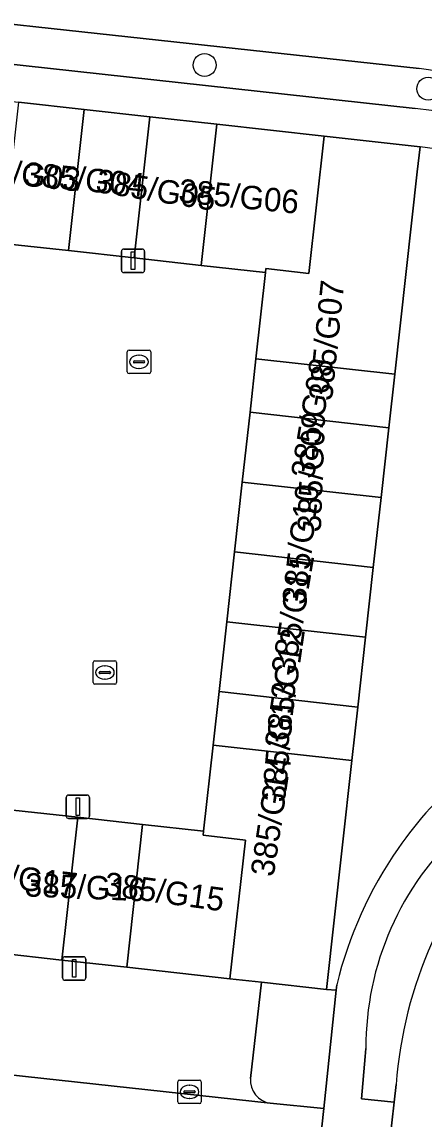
# Model space of a CAD drawing. Extents: x 162026 to 163502, y 387295 to 388169.
# Drawn here: x 162161.01 to 162178.15, y 387792.93 to 387839.64 of the extents above; entities that cross this region are included whole.
import ezdxf

# ---------------------------------------------------------------- set-up
doc = ezdxf.new("R2010")
doc.units = 0
for name, color, linetype in [('IMGEO_Boom', 7, 'Continuous'), ('IMGEO_Fietspad_gesloten', 7, 'Continuous'), ('IMGEO_Groenvoorziening', 7, 'Continuous'), ('IMGEO_Kolk', 7, 'Continuous'), ('IMGEO_Lichtmast', 7, 'Continuous'), ('IMGEO_Pand', 7, 'Continuous'), ('IMGEO_Pand_nummerreeks', 7, 'Continuous'), ('IMGEO_Parkeervlak_open', 7, 'Continuous'), ('IMGEO_Rijbaan_lokaal_open', 7, 'Continuous'), ('IMGEO_Voetpad_open', 7, 'Continuous')]:
    doc.layers.add(name, color=color, linetype=linetype)

msp = doc.modelspace()

# ---------------------------------------------------------------- linework, layer by layer
at = {"layer": 'IMGEO_Boom'}
for centre in [(162168.793, 387837.806), (162178.326, 387836.8)]:
    msp.add_circle(centre, 0.489, dxfattribs=at)
at = {"layer": 'IMGEO_Fietspad_gesloten'}
msp.add_lwpolyline([(162175.011, 387840.691), (162153.864, 387843.037), (162124.015, 387846.348), (162120.863, 387846.697), (162120.645, 387843.913), (162123.707, 387843.579), (162142.441, 387841.533), (162144.47, 387841.312), (162177.938, 387837.659)], dxfattribs=at)
msp.add_arc((162174.885, 387812.883), 24.963, 19.2399, 82.9748, dxfattribs=at)
at = {"layer": 'IMGEO_Groenvoorziening'}
for points in [[(162144.47, 387841.312), (162144.349, 387839.619), (162177.764, 387835.959)], [(162177.938, 387837.659), (162144.47, 387841.312)], [(162177.973, 387834.328), (162177.854, 387833.262), (162176.897, 387824.645), (162176.643, 387822.366), (162176.313, 387819.393), (162175.983, 387816.419), (162175.652, 387813.445), (162175.322, 387810.471), (162175.068, 387808.19), (162174.655, 387804.471), (162173.985, 387798.447), (162174.399, 387798.411), (162174.423, 387798.647)], [(162174.399, 387798.411), (162173.985, 387798.447), (162171.221, 387798.754), (162170.746, 387794.657)], [(162171.589, 387793.598), (162173.877, 387793.382), (162174.399, 387798.411)], [(162175.666, 387795.93), (162175.642, 387795.586), (162175.477, 387793.792), (162176.873, 387793.647), (162176.954, 387794.397)]]:
    msp.add_lwpolyline(points, dxfattribs=at)
for centre, radius, start, end in [((162174.885, 387812.883), 24.963, 19.2399, 82.9748), ((162175.651, 387814.372), 21.69, 25.9544, 84.4086), ((162175.575, 387814.095), 20.374, 26.678, 83.2402), ((162191.407, 387794.495), 17.477, 130.9104, 145.2692), ((162195.063, 387793.031), 18.161, 136.1983, 175.6852), ((162188.185, 387795.99), 12.519, 132.1359, 180.2763), ((162191.436, 387794.462), 17.52, 145.2363, 166.181), ((162171.751, 387794.592), 1.007, 176.3125, 260.7294)]:
    msp.add_arc(centre, radius, start, end, dxfattribs=at)
at = {"layer": 'IMGEO_Kolk'}
for p, q in [((162165.574, 387825.67), (162166.426, 387825.67)), ((162165.499, 387824.744), (162165.499, 387825.596)), ((162165.801, 387825.213), (162166.199, 387825.213)), ((162165.987, 387825.45), (162166.012, 387825.45)), ((162166.5, 387825.596), (162166.5, 387824.744)), ((162165.758, 387825.164), (162165.758, 387825.176)), ((162166.196, 387825.127), (162165.798, 387825.127)), ((162166.01, 387824.89), (162165.985, 387824.89)), ((162166.242, 387825.176), (162166.242, 387825.164)), ((162166.426, 387824.67), (162165.574, 387824.67)), ((162164.045, 387811.514), (162164.045, 387812.366)), ((162164.12, 387812.44), (162164.972, 387812.44)), ((162164.533, 387812.22), (162164.558, 387812.22)), ((162165.046, 387812.366), (162165.046, 387811.514)), ((162164.304, 387811.934), (162164.304, 387811.946)), ((162164.742, 387811.897), (162164.344, 387811.897)), ((162164.347, 387811.983), (162164.745, 387811.983)), ((162164.556, 387811.66), (162164.531, 387811.66)), ((162164.788, 387811.946), (162164.788, 387811.934)), ((162164.972, 387811.44), (162164.12, 387811.44)), ((162167.651, 387793.66), (162167.651, 387794.512)), ((162167.726, 387794.586), (162168.578, 387794.586)), ((162168.139, 387794.366), (162168.164, 387794.366)), ((162168.652, 387794.512), (162168.652, 387793.66)), ((162167.91, 387794.08), (162167.91, 387794.092)), ((162168.348, 387794.043), (162167.95, 387794.043)), ((162167.953, 387794.129), (162168.351, 387794.129)), ((162168.394, 387794.092), (162168.394, 387794.08)), ((162168.578, 387793.586), (162167.726, 387793.586)), ((162168.162, 387793.806), (162168.137, 387793.806))]:
    msp.add_line(p, q, dxfattribs=at)
for points in [[(162165.574, 387825.67), (162166.426, 387825.67)], [(162165.499, 387824.744), (162165.499, 387825.596)], [(162166.5, 387825.596), (162166.5, 387824.744)], [(162166.426, 387824.67), (162165.574, 387824.67)], [(162164.045, 387811.514), (162164.045, 387812.366)], [(162164.12, 387812.44), (162164.972, 387812.44)], [(162165.046, 387812.366), (162165.046, 387811.514)], [(162164.972, 387811.44), (162164.12, 387811.44)], [(162167.651, 387793.66), (162167.651, 387794.512)], [(162167.726, 387794.586), (162168.578, 387794.586)], [(162168.652, 387794.512), (162168.652, 387793.66)], [(162168.578, 387793.586), (162167.726, 387793.586)]]:
    msp.add_lwpolyline(points, dxfattribs=at)
for centre, radius, start, end in [((162165.576, 387825.594), 0.0765, 91.552, 178.448), ((162165.576, 387825.594), 0.0765, 91.552, 178.448), ((162166.424, 387825.594), 0.0765, 1.552, 88.448), ((162166.424, 387825.594), 0.0765, 1.552, 88.448), ((162165.798, 387825.173), 0.0403, 85.8775, 175.7526), ((162166.203, 387825.175), 0.0386, 1.7309, 96.639), ((162165.576, 387824.746), 0.0765, 181.552, 268.448), ((162165.576, 387824.746), 0.0765, 181.552, 268.448), ((162165.795, 387825.163), 0.0366, 178.938, 274.7102), ((162166.199, 387825.17), 0.043, 264.8664, 352.4533), ((162166.424, 387824.746), 0.0765, 271.552, 358.448), ((162166.424, 387824.746), 0.0765, 271.552, 358.448), ((162164.122, 387812.364), 0.0765, 91.552, 178.448), ((162164.122, 387812.364), 0.0765, 91.552, 178.448), ((162164.97, 387812.364), 0.0765, 1.552, 88.448), ((162164.97, 387812.364), 0.0765, 1.552, 88.448), ((162164.344, 387811.943), 0.0403, 85.8775, 175.7526), ((162164.341, 387811.933), 0.0366, 178.938, 274.7102), ((162164.745, 387811.94), 0.043, 264.8664, 352.4533), ((162164.749, 387811.945), 0.0386, 1.7309, 96.639), ((162164.122, 387811.516), 0.0765, 181.552, 268.448), ((162164.122, 387811.516), 0.0765, 181.552, 268.448), ((162164.97, 387811.516), 0.0765, 271.552, 358.448), ((162164.97, 387811.516), 0.0765, 271.552, 358.448), ((162167.728, 387794.51), 0.0765, 91.552, 178.448), ((162167.728, 387794.51), 0.0765, 91.552, 178.448), ((162168.576, 387794.51), 0.0765, 1.552, 88.448), ((162168.576, 387794.51), 0.0765, 1.552, 88.448), ((162167.95, 387794.089), 0.0403, 85.8775, 175.7526), ((162167.947, 387794.079), 0.0366, 178.938, 274.7102), ((162168.351, 387794.086), 0.043, 264.8664, 352.4533), ((162168.355, 387794.091), 0.0386, 1.7309, 96.639), ((162167.728, 387793.662), 0.0765, 181.552, 268.448), ((162167.728, 387793.662), 0.0765, 181.552, 268.448), ((162168.576, 387793.662), 0.0765, 271.552, 358.448), ((162168.576, 387793.662), 0.0765, 271.552, 358.448)]:
    msp.add_arc(centre, radius, start, end, dxfattribs=at)
for centre, major_axis, ratio, start_param, end_param in [((162165.986, 387825.17), (-0.387, 0.002), 0.722429, 4.712389, 7.853982), ((162166.011, 387825.17), (-0.39, 0.002), 0.717154, 1.570796, 4.712389), ((162164.532, 387811.94), (-0.387, 0.002), 0.722429, 4.712389, 7.853982), ((162164.557, 387811.94), (-0.39, 0.002), 0.717154, 1.570796, 4.712389), ((162168.138, 387794.086), (-0.387, 0.002), 0.722429, 4.712389, 7.853982), ((162168.163, 387794.086), (-0.39, 0.002), 0.717154, 1.570796, 4.712389)]:
    msp.add_ellipse(centre, major_axis=major_axis, ratio=ratio, start_param=start_param, end_param=end_param, dxfattribs=at)
at = {"layer": 'IMGEO_Lichtmast'}
for p, q in [((162165.248, 387829.073), (162165.248, 387829.873)), ((162165.248, 387829.873), (162165.248, 387829.073)), ((162165.348, 387829.973), (162166.138, 387829.973)), ((162166.138, 387829.973), (162165.348, 387829.973)), ((162166.238, 387829.873), (162166.238, 387829.073)), ((162166.238, 387829.073), (162166.238, 387829.873)), ((162166.138, 387828.973), (162165.348, 387828.973)), ((162165.348, 387828.973), (162166.138, 387828.973)), ((162162.9, 387805.825), (162162.9, 387806.625)), ((162162.9, 387806.625), (162162.9, 387805.825)), ((162163, 387806.725), (162163.79, 387806.725)), ((162163.79, 387806.725), (162163, 387806.725)), ((162163.89, 387806.625), (162163.89, 387805.825)), ((162163.89, 387805.825), (162163.89, 387806.625)), ((162163.79, 387805.725), (162163, 387805.725)), ((162163, 387805.725), (162163.79, 387805.725)), ((162162.743, 387798.94), (162162.743, 387799.74)), ((162162.743, 387799.74), (162162.743, 387798.94)), ((162162.843, 387799.84), (162163.633, 387799.84)), ((162163.633, 387799.84), (162162.843, 387799.84)), ((162163.733, 387799.74), (162163.733, 387798.94)), ((162163.733, 387798.94), (162163.733, 387799.74)), ((162163.633, 387798.84), (162162.843, 387798.84)), ((162162.843, 387798.84), (162163.633, 387798.84))]:
    msp.add_line(p, q, dxfattribs=at)
for points in [[(162165.668, 387829.848), (162165.818, 387829.848), (162165.818, 387829.098), (162165.668, 387829.098), (162165.668, 387829.848)], [(162163.32, 387806.6), (162163.47, 387806.6), (162163.47, 387805.85), (162163.32, 387805.85), (162163.32, 387806.6)], [(162163.163, 387799.715), (162163.313, 387799.715), (162163.313, 387798.965), (162163.163, 387798.965), (162163.163, 387799.715)]]:
    msp.add_lwpolyline(points, dxfattribs=at)
for centre, start, end in [((162165.348, 387829.873), 90, 180), ((162165.348, 387829.873), 90, 180), ((162166.138, 387829.873), 0, 90), ((162166.138, 387829.873), 360, 90), ((162165.348, 387829.073), 180, 270), ((162165.348, 387829.073), 180, 270), ((162166.138, 387829.073), 270, 0), ((162166.138, 387829.073), 270, 0), ((162163, 387806.625), 90, 180), ((162163, 387806.625), 90, 180), ((162163.79, 387806.625), 0, 90), ((162163.79, 387806.625), 360, 90), ((162163, 387805.825), 180, 270), ((162163, 387805.825), 180, 270), ((162163.79, 387805.825), 270, 0), ((162163.79, 387805.825), 270, 0), ((162162.843, 387799.74), 90, 180), ((162162.843, 387799.74), 90, 180), ((162163.633, 387799.74), 0, 90), ((162163.633, 387799.74), 360, 90), ((162162.843, 387798.94), 180, 270), ((162162.843, 387798.94), 180, 270), ((162163.633, 387798.94), 270, 0), ((162163.633, 387798.94), 270, 0)]:
    msp.add_arc(centre, 0.1, start, end, dxfattribs=at)
at = {"layer": 'IMGEO_Pand'}
for points in [[(162162.997, 387829.904), (162163.666, 387835.918), (162160.868, 387836.229), (162160.2, 387830.215)], [(162165.795, 387829.593), (162166.464, 387835.607), (162163.666, 387835.918), (162162.997, 387829.904)], [(162168.645, 387829.276), (162169.313, 387835.29), (162166.464, 387835.607), (162165.795, 387829.593)], [(162171.391, 387828.971), (162171.409, 387829.139), (162173.236, 387828.935), (162173.885, 387834.782), (162169.313, 387835.29), (162168.645, 387829.276)], [(162170.983, 387825.303), (162176.897, 387824.645), (162177.854, 387833.262), (162177.973, 387834.328), (162173.885, 387834.782), (162173.236, 387828.935), (162171.409, 387829.139), (162171.391, 387828.971)], [(162170.73, 387823.024), (162176.643, 387822.366), (162176.897, 387824.645), (162170.983, 387825.303)], [(162170.399, 387820.05), (162176.313, 387819.393), (162176.643, 387822.366), (162170.73, 387823.024)], [(162170.069, 387817.076), (162175.983, 387816.419), (162176.313, 387819.393), (162170.399, 387820.05)], [(162169.738, 387814.102), (162175.652, 387813.445), (162175.983, 387816.419), (162170.069, 387817.076)], [(162169.408, 387811.128), (162175.322, 387810.471), (162175.652, 387813.445), (162169.738, 387814.102)], [(162169.155, 387808.848), (162175.068, 387808.19), (162175.322, 387810.471), (162169.408, 387811.128)], [(162174.655, 387804.471), (162175.068, 387808.19), (162169.155, 387808.848), (162168.747, 387805.181), (162168.726, 387805.011), (162170.532, 387804.81), (162169.875, 387798.904), (162171.221, 387798.754), (162173.985, 387798.447)], [(162160.629, 387806.083), (162159.953, 387800.006), (162162.714, 387799.7), (162163.39, 387805.777)], [(162163.39, 387805.777), (162162.714, 387799.7), (162165.475, 387799.393), (162166.151, 387805.47)], [(162166.151, 387805.47), (162165.475, 387799.393), (162169.875, 387798.904), (162170.532, 387804.81), (162168.726, 387805.011), (162168.747, 387805.181)]]:
    msp.add_lwpolyline(points, close=True, dxfattribs=at)
at = {"layer": 'IMGEO_Parkeervlak_open'}
for points in [[(162171.221, 387798.754), (162169.875, 387798.904), (162165.475, 387799.393), (162162.714, 387799.7), (162159.953, 387800.006), (162155.422, 387800.51), (162151.274, 387800.971), (162150.824, 387796.88)], [(162170.746, 387794.657), (162171.221, 387798.754)], [(162149.817, 387795.974), (162171.589, 387793.598)]]:
    msp.add_lwpolyline(points, dxfattribs=at)
msp.add_arc((162171.751, 387794.592), 1.007, 176.3125, 260.7294, dxfattribs=at)
at = {"layer": 'IMGEO_Rijbaan_lokaal_open'}
for points in [[(162171.391, 387828.971), (162168.645, 387829.276), (162165.795, 387829.593), (162162.997, 387829.904), (162160.2, 387830.215), (162157.402, 387830.526), (162154.604, 387830.837), (162154.461, 387830.83), (162141.717, 387832.294), (162128.746, 387833.776), (162128.1, 387828.045)], [(162159.786, 387823.383), (162159.777, 387823.278), (162159.965, 387823.257), (162159.635, 387820.293), (162159.328, 387817.53), (162159.018, 387814.739), (162158.708, 387811.948), (162158.412, 387809.293), (162158.087, 387806.366), (162160.629, 387806.083), (162163.39, 387805.777), (162166.151, 387805.47), (162168.747, 387805.181), (162169.155, 387808.848), (162169.408, 387811.128), (162169.738, 387814.102), (162170.069, 387817.076), (162170.399, 387820.05), (162170.73, 387823.024), (162170.983, 387825.303), (162171.391, 387828.971)], [(162140.87, 387825.929), (162140.291, 387820.827), (162136.99, 387791.294), (162142.91, 387790.674), (162154.304, 387789.45), (162156.006, 387789.258), (162172.346, 387787.49), (162172.43, 387787.481), (162173.226, 387787.405), (162173.877, 387793.382), (162171.589, 387793.598), (162149.817, 387795.974), (162145.027, 387796.502)], [(162176.954, 387794.397), (162176.873, 387793.647), (162176.767, 387792.767), (162176.029, 387786.281), (162175.451, 387780.914), (162175.197, 387778.502), (162174.638, 387773.728)]]:
    msp.add_lwpolyline(points, dxfattribs=at)
msp.add_arc((162195.063, 387793.031), 18.161, 136.1983, 175.6852, dxfattribs=at)
at = {"layer": 'IMGEO_Voetpad_open'}
for points in [[(162177.764, 387835.959), (162144.349, 387839.619), (162144.47, 387841.312), (162142.441, 387841.533), (162142.287, 387839.823), (162124.231, 387841.861), (162123.536, 387841.932), (162123.364, 387840.416), (162129.386, 387839.759), (162142.079, 387838.375), (162141.978, 387837.533), (162141.753, 387837.294)], [(162144.266, 387837.04), (162144.066, 387837.252), (162144.169, 387838.128), (162155.272, 387836.851), (162158.07, 387836.54), (162160.868, 387836.229), (162163.666, 387835.918), (162166.464, 387835.607), (162169.313, 387835.29), (162173.885, 387834.782), (162177.973, 387834.328)], [(162174.423, 387798.647), (162174.399, 387798.411), (162173.877, 387793.382), (162173.226, 387787.405), (162172.67, 387782.382), (162172.543, 387781.229), (162172.275, 387778.829), (162171.946, 387775.897), (162171.441, 387771.387), (162171.433, 387770.804)], [(162174.638, 387773.728), (162173.273, 387773.889), (162173.794, 387778.646), (162175.197, 387778.502), (162175.451, 387780.914), (162174.076, 387781.053), (162174.638, 387786.435), (162176.029, 387786.281), (162176.767, 387792.767), (162176.873, 387793.647), (162175.477, 387793.792), (162175.642, 387795.586), (162175.666, 387795.93)]]:
    msp.add_lwpolyline(points, dxfattribs=at)
for centre, radius, start, end in [((162175.651, 387814.372), 21.69, 25.9544, 84.4086), ((162175.575, 387814.095), 20.374, 26.678, 83.2402), ((162191.407, 387794.495), 17.477, 130.9104, 145.2692), ((162188.185, 387795.99), 12.519, 132.1359, 180.2763), ((162191.436, 387794.462), 17.52, 145.2363, 166.181)]:
    msp.add_arc(centre, radius, start, end, dxfattribs=at)

# ---------------------------------------------------------------- texts
at = {"layer": 'IMGEO_Pand_nummerreeks'}
for s, rotation, p in [('385/G03', 353.8845, (162158.349, 387832.963)), ('385/G04', 354.4007, (162161.076, 387832.694)), ('385/G05', 350.8698, (162164.118, 387832.407)), ('385/G06', 354.3595, (162167.655, 387831.974)), ('385/G07', 84.1226, (162174.224, 387823.485)), ('385/G08', 80.5377, (162173.445, 387820.16)), ('385/G09', 87.8789, (162173.746, 387817.906)), ('385/G10', 83.2902, (162173.083, 387814.796)), ('385/G11', 80.3625, (162172.611, 387811.82)), ('385/G12', 81.7241, (162172.336, 387808.668)), ('385/G13', 84.8056, (162172.219, 387806.395)), ('385/G14', 81.509, (162171.734, 387803.21)), ('385/G17', 353.1572, (162158.213, 387803.015)), ('385/G16', 357.6141, (162161.119, 387802.41)), ('385/G15', 352.1709, (162164.473, 387802.466))]:
    msp.add_text(s, height=1, rotation=rotation, dxfattribs=at).set_placement(p)

doc.saveas('drawing.dxf')
